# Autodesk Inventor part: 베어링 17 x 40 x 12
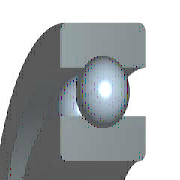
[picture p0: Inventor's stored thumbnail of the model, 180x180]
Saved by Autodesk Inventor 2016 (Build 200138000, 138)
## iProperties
IsCustomPart: 1
Created: 2012-02
Part Number: 베어링 17 x 40 x 12
Material: 강철, 연강
Description: 깊은 그루브 볼 베어링
Document SubType Name: Modeling
Standard: KS B 2023
Designer: mduedu
Standards Organization: KS
Language: ko-KR
Size Designation: 6203 - 17 x 40 x 12
Categories: <MemberInstance><Categories><Category DisplayName="샤프트 부품" InternalName="7f7aeb1f-a693-4053-b835-cee3144e0d98" Mnemonic="SHFT"><Category DisplayName="베어링" Inter
Density: 1 g/cm^3
Appearance: 노란색
Author: mduedu
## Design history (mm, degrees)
sketch "스케치" dims "d0" = 5.98 (= -0.26 x WD + 0.26 x BD)
  geometry: L1 (3.01, 14.25)-(8.99, 14.25); L2 (6, 14.25)-(6, 11.26); L3 (6, 14.25)-(6, 17.24); L4 (3.778, 12.249)-(0, 12.249); L5 (0, 8.5)-(12, 8.5); L6 (3.778, 16.251)-(0, 16.251); L7 (0, 20)-(12, 20); L8 (12, 8.5)-(12, 12.249); L9 (8.222, 12.249)-(12, 12.249); L10 (8.222, 16.251)-(12, 16.251); L11 (12, 20)-(12, 16.251); L12 (-1.4, 0)-(8.4, 0) reference; L13 (0, -0.3)-(0, 5.3) reference
  constraints: 22 end point, 4 point on line, 2 collinear, 2 perpendicular, 2 symmetric about line, 1 midpoint, 1 parallel, 14 other
  dimensions: "d9" = 17 diameter of L5 L12 (= WD); "d11" = 40 diameter of L7 L12 (= BD); "d12" = 12 distance between parallel lines of L8 L13 (= KB); "d13" = 24.498 diameter of L9 L12 (= 0.326 x BD + 0.674 x WD)
revolve "본체" stored, may be unused: angle "d6" = 90 deg
revolve "볼" stored, may be unused: angle "d7" = 90 deg
pattern_circular "IDS_ARRAYBALL[SIMPL:T]" dims angle "d3" = 360 deg
body "Solid1"
fillet "모깎기1" dims "d1" = 0.6 (= KRS)
other parameters: "WD" = 17 [user parameter; used in 5 equation terms], "BD" = 40 [user parameter; used in 5 equation terms], "KB" = 12 [user parameter; used in 1 equation term], "KRS" = 0.6 [user parameter; used in 1 equation term], "d4" = 0, "d5" = 0, "d8" = 0, "d14" = 0, "d15" = 0, "BBA" = 0 [user parameter], "BC0" = 4750000 [user parameter], "BC" = 9560000 [user parameter], "WR" = 8.5 (= 0.5 x WD) [user parameter]
